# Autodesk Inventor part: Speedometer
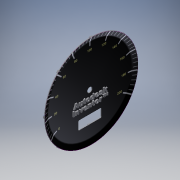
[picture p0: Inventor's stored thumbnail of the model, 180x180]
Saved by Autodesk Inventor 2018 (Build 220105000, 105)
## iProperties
Company: Autodesk, Inc.
Shininess: 64.0
Length Units: 11272
Angle Units: 11279
Time Units: 11290
Mass Units: 11286
Length Display Precision: 3
Angle Display Precision: 2
Compacted: True
Part Number: Speedometer
Document SubType Name: Modeling
Created: 2002-09
Stock Number: PRL-534-B
Density: 1 g/cm^3
Mass: 7.02363 g
Surface Area: 170.355 cm^2
Volume: 7.02363 cm^3
Material: Generic
Appearance: Default
Designer: Autodesk, Inc.
Density: 0.0
Volumn: 0.0
Area: 0.0
PropertySet Name: Model Information
Control State: 0
Master: False
Checked Out: False
Author: Autodesk, Inc.
Revision Number: A
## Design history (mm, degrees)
sketch "Sketch1"
  geometry: L1 (0, 0)-(-45.72, 0); L2 (-45.72, 0)-(-50.8, 1.849); L3 (0, -26.18)-(0, 27.22) reference; L4 (-44.342, 19.592)-(-58.225, -18.551)
  constraints: 6 end point, 1 horizontal, 1 perpendicular, 1 point on line
  dimensions: "d0" = 45.72 distance of L1.start L1.end; "d1" = 50.8 horizontal distance of L1.start L2.end; "d2" = 160 deg angle of L1 L2
feature "RevolutionSrf1" dims angle "d3" = 90 deg
fillet "Fillet1" dims "d4" = 3.175
thicken "Thicken1" dims "d5" = 0.762
sketch "Sketch2"
  geometry: L1 (-1.27, 65.322)-(-1.27, 16.574); L2 (1.27, 16.574)-(1.27, 65.322); L3 (0, 0)-(0, 66.507); L4 (-10.821, 12.617)-(-45.291, 47.088); L5 (-47.088, 45.291)-(-12.617, 10.821); L6 (-16.574, 1.27)-(-65.322, 1.27); L7 (-65.322, -1.27)-(-16.574, -1.27); L8 (-12.617, -10.821)-(-47.088, -45.291); L9 (-45.291, -47.088)-(-10.821, -12.617); L10 (-1.27, -16.574)-(-1.27, -65.322); L11 (1.27, -65.322)-(1.27, -16.574); L12 (10.821, -12.617)-(45.291, -47.088); L13 (47.088, -45.291)-(12.617, -10.821); L14 (16.574, -1.27)-(65.322, -1.27); L15 (65.322, 1.27)-(16.574, 1.27); L16 (12.617, 10.821)-(47.088, 45.291); L17 (45.291, 47.088)-(10.821, 12.617); C1 r 14.082 at (0, 0); C2 r 45.16 at (0, 0) reference; A1 r 65.334 centre (0, 0) between (1.27, 65.322) and (-1.27, 65.322); A2 r 65.334 centre (0, 0) between (-45.291, 47.088) and (-47.088, 45.291); A3 r 65.334 centre (0, 0) between (-65.322, 1.27) and (-65.322, -1.27); A4 r 65.334 centre (0, 0) between (-47.088, -45.291) and (-45.291, -47.088); A5 r 65.334 centre (0, 0) between (-1.27, -65.322) and (1.27, -65.322); A6 r 65.334 centre (0, 0) between (45.291, -47.088) and (47.088, -45.291); A7 r 65.334 centre (0, 0) between (65.322, -1.27) and (65.322, 1.27); A8 r 65.334 centre (0, 0) between (47.088, 45.291) and (45.291, 47.088); A9 r 16.622 centre (0, 0) between (-12.617, 10.821) and (-16.574, 1.27); A10 r 16.622 centre (0, 0) between (-16.574, -1.27) and (-12.617, -10.821); A11 r 16.622 centre (0, 0) between (-10.821, -12.617) and (-1.27, -16.574); A12 r 16.622 centre (0, 0) between (1.27, -16.574) and (10.821, -12.617); A13 r 16.622 centre (0, 0) between (12.617, -10.821) and (16.574, -1.27); A14 r 16.622 centre (0, 0) between (16.574, 1.27) and (12.617, 10.821); A15 r 16.622 centre (0, 0) between (10.821, 12.617) and (1.27, 16.574); A16 r 16.622 centre (0, 0) between (-1.27, 16.574) and (-10.821, 12.617)
  constraints: 34 end point, 32 point on circle, 17 centre point, 3 coincident, 2 parallel, 1 vertical, 65 other
  dimensions: "d101" = 2.54 distance between parallel lines of L2 L1; "d105" = 360 deg dimension on A9.centre L2.start (derived)
feature "Sculpt1"
fillet "Fillet8" dims "d67" = 2.54
fillet "Fillet9" dims "d68" = 0.3175
fillet "Fillet10" dims "d69" = 0.3175
workplane "Work Plane1"
sketch "Sketch8"
  geometry: L1 (-12.7, -32.385)-(12.7, -32.385); L2 (12.7, -32.385)-(12.7, -22.86); L3 (12.7, -22.86)-(-12.7, -22.86); L4 (-12.7, -22.86)-(-12.7, -32.385); 1 further point
  constraints: 8 end point, 2 parallel, 1 horizontal, 1 perpendicular
  dimensions: "d109" = 25.4 distance of L1.start L1.end; "d110" = 9.525 distance of L1.end L2.end; "d111" = 12.7 distance from line of L4 point (0, 0) (derived); "d112" = 22.86 distance from line of point (0, 0) L3
extrude "Extrusion3" cut sketch "Sketch8" extent not by distance; stored distance "d113" = 25.4; taper "d114" = 0 deg
fillet "Fillet2" dims "d53" = 1.27
sketch "Sketch5"
  geometry: L1 (25.429, 19.589)-(-25.429, 19.589); L2 (-25.429, 19.589)-(-25.429, 1.055); L3 (-25.429, 1.055)-(25.429, 1.055); L4 (25.429, 1.055)-(25.429, 19.589); L5 (0, 1.055)-(0, 22.86)
  constraints: 2 end point, 1 midpoint, 1 perpendicular, 2 other
emboss "Emboss1" sketch "Sketch5" dims "d25" = 1.27, "d26" = 0
sketch "Sketch9"
  geometry: C1 r 45.16 at (0, 0) reference; C2 r 2.54 at (0, 0)
  constraints: 1 centre point, 1 coincident
  dimensions: "d115" = 5.08 diameter of C2
extrude "Extrusion4" cut sketch "Sketch9" extent not by distance; stored distance "d116" = 25.4; taper "d117" = 0 deg
fillet "Fillet3" dims "d54" = 0.3175
body "Solid1"
feature "Decal1"
feature "Decal3"
body "Srf1"
sketch "Sketch3"
  geometry: L1 (-50.8, 0)-(50.8, 0); L2 (-50.8, 50.8)-(50.8, 50.8); L3 (50.8, 50.8)-(50.8, -50.8); L4 (50.8, -50.8)-(-50.8, -50.8); L5 (-50.8, -50.8)-(-50.8, 50.8); L6 (71.12, 0)-(-71.12, 0) reference; L7 (0, -71.12)-(0, 71.12) reference; 2 further points; 1 other entity
  constraints: 2 end point, 1 coincident, 1 midpoint, 2 other
  dimensions: "d164" = 101.6 distance between parallel lines of L3 L5; "d165" = 50.8 distance between parallel lines of L7 L5 (derived); "d166" = 50.8 distance between parallel lines of L6 L2 (derived)
body "Srf3"
body "Srf4"
body "Srf5"
body "Srf2"
sketch "Sketch10"
  geometry: L1 (4.655, 10.901)-(27.437, 10.901); L2 (27.437, 10.901)-(27.437, 6.004); L3 (27.437, 6.004)-(4.655, 6.004); L4 (4.655, 6.004)-(4.655, 10.901); 1 further point; 1 other entity
  constraints: 2 other
node "Image3"
node "Image4"
extrude_surface "ExtrusionSrf1" dims "d93" = 25.4, "d94" = 0
extrude_surface "ExtrusionSrf2" dims "d95" = 25.4, "d96" = 0
feature "OffsetSrf2" dims "d97" = 0.762, "d98" = 0.762
feature "RevolutionSrf2" dims angle "d99" = 90 deg
other parameters: "d6" = 2.54, "d17" = 12.7, "d84" = 2.54, "d86" = 2.54 (derived)
